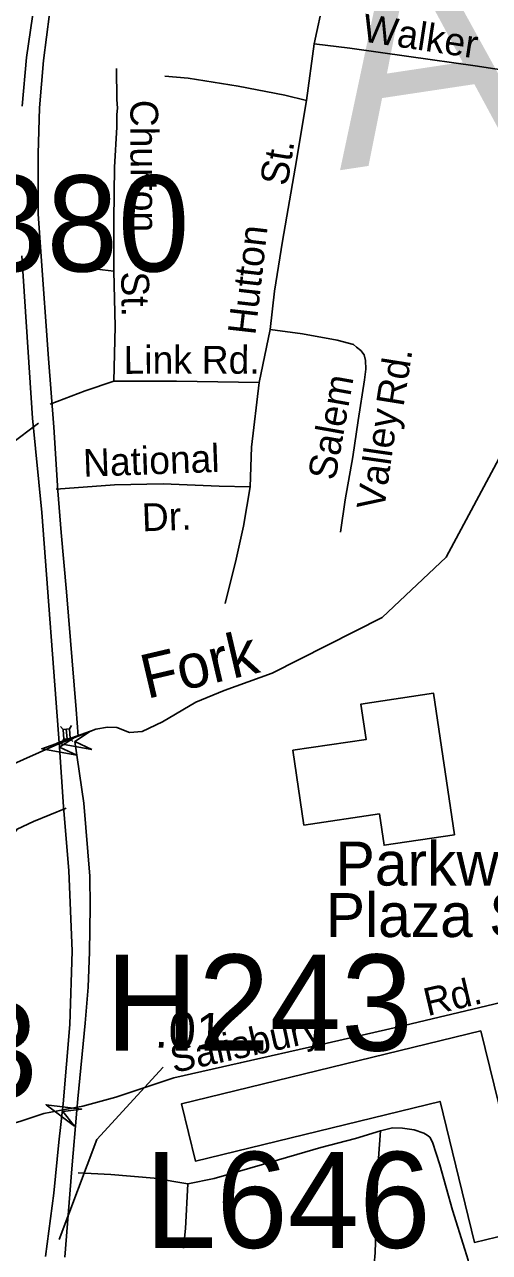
# Model space of a CAD drawing. Extents: x 1553981 to 1780076, y 812965 to 996873.
# Drawn here: x 1632965 to 1633164, y 846800 to 847325 of the extents above; entities that cross this region are included whole.
import ezdxf

# ---------------------------------------------------------------- set-up
doc = ezdxf.new("R2010")
doc.units = 0
for name, color, linetype in [('Exist Aviation Military CELL', 7, 'Continuous'), ('Exist Cultural Educational Facility High CELL', 7, 'Continuous'), ('Exist Cultural Shopping Center Building Footprint', 7, 'Continuous'), ('Exist Hydrographic Creek Single Shore', 7, 'Continuous'), ('Exist Hydrographic Creek Single Shore Label', 7, 'Continuous'), ('Exist Road Non-System Structure Non-Sys Other Number Label', 7, 'Continuous'), ('Exist Road Non-System Type 51 Label', 7, 'Continuous'), ('Exist Road Primary Interstate Structure Cantilever Sign Number Label', 7, 'Continuous'), ('Exist Road Primary NC Service Mileage Hundredths English Label', 7, 'Continuous'), ('Exist Road Primary NC UnDivided 4 Lane Attributed', 7, 'Continuous'), ('Exist Road Primary US Structure Non-Sys NCDOT Number Label', 7, 'Continuous'), ('Exist Road Secondary Structure Culvert Number Label', 7, 'Continuous'), ('Exist Road Secondary Structure Standard Bridge Attributed CELL', 7, 'Continuous'), ('Map Preparation Border County Name Lower Right Label', 7, 'Continuous'), ('Map Preparation County Inset Title Block CELL', 7, 'Continuous')]:
    doc.layers.add(name, color=color, linetype=linetype)

msp = doc.modelspace()

# ---------------------------------------------------------------- linework, layer by layer
at = {"layer": 'Exist Cultural Educational Facility High CELL'}
for p, q in [((1632985.25, 847025.25), (1632984.4, 847023.84)), ((1632980.58, 847024.88), (1632981.64, 847023.62)), ((1632983.02, 847023.73), (1632983.35, 847019.59)), ((1632982, 847019.48), (1632981.15, 847018.06)), ((1632984.72, 847019.7), (1632985.79, 847018.43))]:
    msp.add_line(p, q, dxfattribs=at)
msp.add_lwpolyline([(1632981.64, 847023.62), (1632981.97, 847019.48), (1632984.73, 847019.7), (1632984.4, 847023.84)], close=True, dxfattribs=at)
at = {"layer": 'Exist Cultural Shopping Center Building Footprint'}
for points in [[(1633148.7, 846978.63), (1633139.74, 847039.05), (1633108.78, 847034.45), (1633111.02, 847019.37), (1633079.72, 847014.73), (1633084.46, 846982.77), (1633116.64, 846987.55), (1633118.62, 846974.16)], [(1633160, 846894.96), (1633032.18, 846863.81), (1633038.14, 846839.33), (1633142.54, 846864.78), (1633157.21, 846804.58), (1633180.64, 846810.29)]]:
    msp.add_lwpolyline(points, close=True, dxfattribs=at)
at = {"layer": 'Exist Hydrographic Creek Single Shore'}
msp.add_lwpolyline([(1632917.18, 846975.8), (1632932.11, 846987.72), (1632956.76, 847007.18), (1632979.41, 847017.37), (1632988.13, 847020.71), (1632995.6, 847023.75), (1633000.59, 847024.52), (1633004.53, 847024.38), (1633010, 847022.23), (1633015.33, 847022.72), (1633024.06, 847026.87), (1633038.32, 847035.31), (1633050.36, 847040.16), (1633070.89, 847047.68), (1633117.82, 847071.4), (1633145.21, 847097.1), (1633180.58, 847163.27), (1633197.46, 847179.75), (1633228.96, 847196.75), (1633274.9, 847241.63), (1633299.11, 847271.57)], dxfattribs=at)
at = {"layer": 'Exist Road Primary NC Service Mileage Hundredths English Label'}
msp.add_lwpolyline([(1632980.02, 846805.79), (1632996.03, 846848.47), (1633024.31, 846879.42)], dxfattribs=at)
at = {"layer": 'Exist Road Primary NC UnDivided 4 Lane Attributed'}
for points in [[(1633011.61, 847832.79), (1633009.34, 847827.58), (1633007.08, 847820.02), (1633005.48, 847808.28), (1633005.37, 847803.81), (1633005.32, 847793.78), (1633005.51, 847788.51), (1633005.8, 847780.79), (1633005.52, 847736.53), (1633007.67, 847678.15), (1633008.97, 847635.18), (1633007.95, 847594), (1633004.38, 847566.27), (1632996.96, 847524.47), (1632988.37, 847466.08), (1632979.71, 847410.92), (1632975.11, 847372.78), (1632965.98, 847310.54), (1632964.11, 847289.64)], [(1632988.13, 847020.71), (1632987.16, 847032.13), (1632983.14, 847082.3), (1632980.78, 847107.61), (1632979.43, 847125.5), (1632977.74, 847152.59), (1632975.38, 847181.96), (1632972.14, 847227.55), (1632971.03, 847243.67), (1632971, 847269.38), (1632971.52, 847288.95), (1632973.25, 847309.23), (1632978.45, 847349.14), (1633009.15, 847552.9), (1633015.04, 847591.8), (1633016.22, 847684.91), (1633011.32, 847786.71)], [(1632963.97, 847225.82), (1632968.54, 847156.52), (1632972.55, 847116.15), (1632980.15, 847015.97)], [(1632980.15, 847015.97), (1632981.83, 846990.6), (1632984.04, 846963.32), (1632985.5, 846928.99), (1632984.53, 846897.63), (1632981.62, 846863.78)], [(1632987.89, 846865.97), (1632991.04, 846898.25), (1632992.35, 846913.55), (1632992.9, 846928.64), (1632993.25, 846947.89), (1632993.04, 846960.97), (1632990.55, 846992.19), (1632986.59, 847018.41)], [(1632981.62, 846863.78), (1632979.82, 846847.44), (1632977.68, 846825.57), (1632974.08, 846798.64)], [(1632982.45, 846798.3), (1632985.37, 846836.01), (1632987.52, 846861.09), (1632987.89, 846865.97)]]:
    msp.add_lwpolyline(points, dxfattribs=at)
at = {"layer": 'Exist Road Secondary Structure Standard Bridge Attributed CELL'}
for points in [[(1632987.54, 847012.6), (1632972.55, 847015.37), (1632986.92, 847020.46), (1632980.15, 847015.97)], [(1632993.98, 847015.04), (1632978.99, 847017.81), (1632993.36, 847022.9), (1632986.59, 847018.41)]]:
    msp.add_lwpolyline(points, close=True, dxfattribs=at)
at = {"layer": 'Map Preparation Border County Name Lower Right Label'}
for p, q in [((1633088.85, 847316.33), (1633085.52, 847292.18)), ((1633003.26, 847219.25), (1632993.68, 847220.39)), ((1633069.98, 847194.37), (1633065.26, 847171.7))]:
    msp.add_line(p, q, dxfattribs=at)
for points in [[(1633088.85, 847316.33), (1633092.94, 847335.54), (1633095.14, 847352.54), (1633098.29, 847376.16), (1633101.73, 847403.09), (1633104.57, 847421.99), (1633108.34, 847431.12), (1633114.95, 847445.61), (1633129.43, 847482.14), (1633142.67, 847511.86)], [(1633088.85, 847316.33), (1633104.08, 847314.51), (1633129.25, 847310.9), (1633157.45, 847306.88), (1633184.52, 847302.78), (1633199.72, 847299.84), (1633206.74, 847299.04), (1633211.58, 847298.37), (1633219.92, 847301.19), (1633231.8, 847311.26)], [(1633003.26, 847219.25), (1633003.26, 847240.99), (1633003.58, 847263.66), (1633004.59, 847280.7), (1633004.63, 847286.09), (1633004.86, 847288.79), (1633004.52, 847292.52), (1633004.43, 847305.8)], [(1633025.03, 847302.5), (1633035.06, 847301.67), (1633056.34, 847298.22), (1633076.26, 847294.45), (1633085.52, 847292.18)], [(1633085.52, 847292.18), (1633080.68, 847263.23), (1633075.33, 847232.05), (1633071.87, 847210.75), (1633069.98, 847194.37)], [(1633003.26, 847172.33), (1633003.89, 847195.63), (1633003.26, 847219.25)], [(1633069.98, 847194.37), (1633083.83, 847192.48), (1633098.63, 847189.8), (1633105.55, 847187.91), (1633106.86, 847186.75), (1633108.68, 847185.31), (1633110.15, 847183.48), (1633110.7, 847181.17), (1633110.82, 847177.41), (1633110.33, 847172.92), (1633107.55, 847155.49), (1633105.34, 847140.03), (1633102.04, 847121.58), (1633100.08, 847107.89)], [(1633003.26, 847172.33), (1632991.12, 847168.21), (1632976.12, 847162.42)], [(1633065.26, 847171.7), (1633030.01, 847172.33), (1633003.26, 847172.33)], [(1633065.26, 847171.7), (1633062.12, 847144.14), (1633061.43, 847127.19)], [(1632971.11, 847154.39), (1632959.11, 847145.25), (1632944.18, 847131.47), (1632930.95, 847116.93), (1632923.58, 847107.3), (1632916.64, 847095.9), (1632910.98, 847084.24), (1632907.6, 847075.55), (1632903.13, 847061.13), (1632899.19, 847048.21)], [(1633061.43, 847127.19), (1633048.2, 847127.4), (1633024.36, 847128.39), (1633003.59, 847128.07), (1632978.73, 847126.18)], [(1633061.43, 847127.19), (1633058.66, 847110.44), (1633055.51, 847096.26), (1633050.79, 847077.37)], [(1632983, 846990.02), (1632969.06, 846984.24), (1632962, 846981), (1632952.6, 846968.35), (1632939.37, 846938.06), (1632931.72, 846922.76), (1632927.02, 846911.88), (1632923.49, 846905.41)], [(1633211.16, 846917.31), (1633204.23, 846916.15), (1633193.68, 846913.11), (1633165.5, 846906.32), (1633124.24, 846896.48), (1633091.17, 846888.97), (1633057.26, 846881.26), (1633028.94, 846874.93), (1633010.52, 846868.8), (1633004.16, 846866.63), (1632990.09, 846862.77), (1632982.33, 846861.38), (1632973.4, 846859.6), (1632963.65, 846856.35), (1632952.79, 846853.17), (1632945.23, 846848.02), (1632937.96, 846841.06), (1632933.08, 846835.52), (1632930.03, 846826.36)], [(1633034.9, 846829.56), (1633046.18, 846831.88), (1633066.76, 846837.82), (1633091.6, 846845.19), (1633106.38, 846848.97), (1633117.18, 846852.3)], [(1633117.18, 846852.3), (1633116.24, 846840.57), (1633115.49, 846824.1), (1633114.87, 846800.12), (1633114.37, 846795.25)], [(1633117.18, 846852.3), (1633122.18, 846853.48), (1633126.48, 846853.31), (1633131.52, 846852.71), (1633135.65, 846851.28), (1633137.01, 846850.45), (1633138.11, 846849.5), (1633139.32, 846847.4), (1633142.43, 846837.68), (1633147.86, 846818.36), (1633153.1, 846801.55), (1633154.53, 846797.04), (1633155.26, 846792.89)], [(1632988.1, 846834.36), (1633002.02, 846833.55), (1633020.47, 846832.03), (1633034.9, 846829.56)], [(1633034.9, 846829.56), (1633033.87, 846810.57), (1633033.03, 846802.21)]]:
    msp.add_lwpolyline(points, dxfattribs=at)
at = {"layer": 'Map Preparation County Inset Title Block CELL'}
msp.add_lwpolyline([(1632986.58, 846854.21), (1632974.4, 846863.37), (1632989.53, 846861.52), (1632981.47, 846860.52)], close=True, dxfattribs=at)

# ---------------------------------------------------------------- texts
at = {"layer": 'Exist Aviation Military CELL'}
for s, p in [('Parkway', (1633097.98, 846956.95)), ('Plaza S.C.', (1633093.8, 846934.98))]:
    msp.add_text(s, height=18.75, dxfattribs=at).set_placement(p)
at = {"layer": 'Exist Hydrographic Creek Single Shore Label'}
msp.add_text('Fork', height=18.75, rotation=13.2006, dxfattribs=at).set_placement((1633017.37, 847036.6))
at = {"layer": 'Exist Road Non-System Structure Non-Sys Other Number Label'}
msp.add_text('J380', height=41.01, dxfattribs=at).set_placement((1632916.65, 847219.12))
at = {"layer": 'Exist Road Non-System Type 51 Label'}
for s, height, rotation, p in [('Acadia', 95, 8.5694, (1633099.61, 847262.31)), ('Walker', 11.875, 351.3639, (1633108.85, 847317.43)), ('Churton', 11.875, 270.1886, (1633010.34, 847292.38)), ('St.', 11.875, 80.8189, (1633077.33, 847255.29)), ('Hutton', 11.875, 83.5193, (1633063.69, 847191.67)), ('St.', 11.875, 270.7496, (1633006.43, 847219.06)), ('Link', 11.875, 0.1507, (1633007.5, 847175.41)), ('Rd.', 11.875, 359.9684, (1633040.83, 847175.48)), ('Rd.', 11.875, 80.938, (1633126.91, 847161.08)), ('Salem', 11.875, 79.854, (1633097.76, 847129.54)), ('Valley', 11.875, 81.8486, (1633118.63, 847116.79)), ('National', 11.875, 2.1154, (1632990.38, 847131.42)), ('Dr.', 11.875, 2.1154, (1633015.47, 847108.16)), ('Rd.', 11.875, 13.2541, (1633137.16, 846901.16)), ('Salisbury', 11.875, 12.3963, (1633028.83, 846876.89))]:
    msp.add_text(s, height=height, rotation=rotation, dxfattribs=at).set_placement(p)
at = {"layer": 'Exist Road Primary Interstate Structure Cantilever Sign Number Label'}
msp.add_text('L646', height=41.01, dxfattribs=at).set_placement((1633016.53, 846802.26))
at = {"layer": 'Exist Road Primary NC Service Mileage Hundredths English Label'}
msp.add_text('.01', height=15.625, rotation=357.6338, dxfattribs=at).set_placement((1633020.57, 846887.89))
at = {"layer": 'Exist Road Primary US Structure Non-Sys NCDOT Number Label'}
msp.add_text('H243', height=41.01, dxfattribs=at).set_placement((1632999.73, 846886.49))
at = {"layer": 'Exist Road Secondary Structure Culvert Number Label'}
msp.add_text('C483', height=41.01, dxfattribs=at).set_placement((1632839.68, 846866.17))

doc.saveas('drawing.dxf')
